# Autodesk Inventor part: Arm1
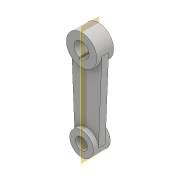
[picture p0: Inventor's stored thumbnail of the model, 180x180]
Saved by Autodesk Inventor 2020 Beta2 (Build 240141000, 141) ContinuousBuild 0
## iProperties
Created: 2016-05
Part Number: Arm1
Material: Generic
Document SubType Name: Modeling
Designer: CADCIM
Density: 1 g/cm^3
Appearance: Default
Author: CADCIM
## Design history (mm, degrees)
sketch "Sketch1"
  geometry: C1 r 56.25 at (0, 0); C2 r 28 at (0, 0); C3 r 43.75 at (0, -300); C4 r 21.75 at (0, -300); 1 further point
  constraints: 4 centre point, 3 coincident
  dimensions: "d0" = 112.5 diameter of C1; "d1" = 56 diameter of C2; "d2" = 87.5 diameter of C3; "d3" = 43.5 diameter of C4; "d4" = 300 distance of C4.centre C2.centre
extrude "Extrusion1" new body sketch "Sketch1" stored distance "d5" = 62.5; taper "d6" = 0 deg
sketch "Sketch2"
  geometry: L1 (56.201, -2.344)-(43.712, -301.823); L2 (-56.201, -2.344)-(-43.712, -301.823); A1 r 56.25 centre (0, 0) between (-56.201, -2.344) and (56.201, -2.344); A2 r 43.75 centre (0, -300) between (43.712, -301.823) and (-43.712, -301.823); 3 further points
  constraints: 4 end point, 4 point on circle, 2 centre point, 2 coincident
extrude "Extrusion2" join sketch "Sketch2" stored distance "d7" = 25; taper "d8" = 0 deg
sketch "Sketch3"
  geometry: L1 (0, 0)-(0, 99.622); L2 (-8, 26.833)-(8, 26.833); L3 (8, 26.833)-(8, 32.3); L4 (8, 32.3)-(-8, 32.3); L5 (-8, 32.3)-(-8, 26.833); L6 (0, 0)-(0, -28); A1 r 28 centre (0, 0) between (-8, 26.833) and (8, 26.833) reference
  constraints: 12 end point, 3 point on circle, 2 parallel, 2 vertical, 1 horizontal, 1 perpendicular, 1 other
  dimensions: "d10" = 16 distance of L3.end L4.end; "d11" = 60.3 distance from line of L4 L6.end
extrude "Extrusion3" cut sketch "Sketch3" extent not by distance; stored distance "d12" = 25; taper "d13" = 0 deg
fillet "Fillet1" dims "d14" = 0.4
body "Solid1"
